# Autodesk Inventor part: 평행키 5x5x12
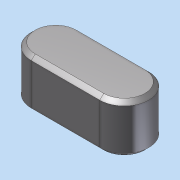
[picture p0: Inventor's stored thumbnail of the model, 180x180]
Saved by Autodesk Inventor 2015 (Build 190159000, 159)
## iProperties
Created: 2024-05
Part Number: 평행키 5x5x12
Material: 일반
Document SubType Name: Modeling
Designer: Administrator
Density: 1 g/cm^3
Appearance: 기본값
Author: Administrator
Author: jhkim
Description: 키 및 해당 키홈
Creation Date: 2024-05-07
Sending System: Autodesk Inventor 2025
Preprocessor: ST-DEVELOPER v20
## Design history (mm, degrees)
node "평행키 5x5x121"
body "Solid1"
node "기준1"
